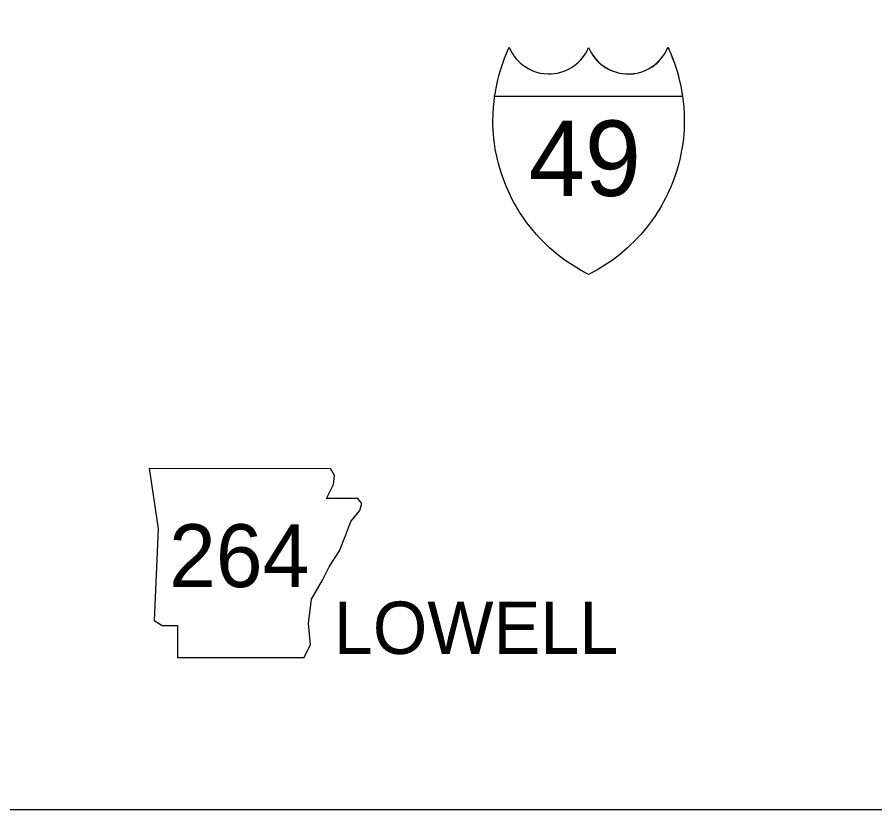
# Model space of a CAD drawing. Extents: x 6028647 to 6035072, y 5366486 to 5368495.
# Drawn here: x 6029148 to 6029256, y 5367916.3 to 5368016.2 of the extents above; entities that cross this region are included whole.
import ezdxf

# ---------------------------------------------------------------- set-up
doc = ezdxf.new("R2010")
doc.units = 0
for name, color, linetype in [('21', 7, 'Continuous'), ('22', 7, 'Continuous'), ('23', 7, 'Continuous'), ('25', 7, 'Continuous'), ('R_NoPlot', 7, 'Continuous')]:
    doc.layers.add(name, color=color, linetype=linetype)

msp = doc.modelspace()

# ---------------------------------------------------------------- linework, layer by layer
at = {"layer": '21'}
for p, q in [((6029164.66, 5367959.35), (6029165.81, 5367951.74)), ((6029188.01, 5367958.46), (6029187.48, 5367959.34)), ((6029187.88, 5367957.32), (6029188.01, 5367958.46)), ((6029187, 5367955.54), (6029187.88, 5367957.32)), ((6029190.93, 5367955.54), (6029187, 5367955.54)), ((6029191.44, 5367954.91), (6029190.93, 5367955.54)), ((6029191.18, 5367954.02), (6029191.44, 5367954.91)), ((6029190.04, 5367952.63), (6029191.18, 5367954.02)), ((6029189.41, 5367950.98), (6029190.04, 5367952.63)), ((6029165.81, 5367951.74), (6029165.3, 5367940.19)), ((6029188.65, 5367948.95), (6029189.41, 5367950.98)), ((6029187.38, 5367947.04), (6029188.65, 5367948.95)), ((6029186.49, 5367945.27), (6029187.38, 5367947.04)), ((6029185.09, 5367942.86), (6029186.49, 5367945.27)), ((6029184.71, 5367939.81), (6029185.09, 5367942.86)), ((6029165.3, 5367940.19), (6029166.31, 5367939.56)), ((6029166.31, 5367939.56), (6029168.22, 5367939.56)), ((6029168.22, 5367939.56), (6029168.22, 5367935.5)), ((6029184.97, 5367937.15), (6029184.71, 5367939.81)), ((6029184.2, 5367935.5), (6029184.97, 5367937.15)), ((6029168.22, 5367935.5), (6029184.2, 5367935.5))]:
    msp.add_line(p, q, dxfattribs=at)
msp.add_lwpolyline([(6029164.66, 5367959.35), (6029187.48, 5367959.34)], dxfattribs=at)
at = {"layer": '23'}
for points in [[(6029208.17, 5368006.18), (6029208.26, 5368006.75), (6029208.35, 5368007.25), (6029208.48, 5368007.89), (6029208.58, 5368008.31), (6029208.7, 5368008.81), (6029208.87, 5368009.4), (6029209.02, 5368009.89), (6029209.19, 5368010.39), (6029209.41, 5368011.01), (6029209.65, 5368011.59), (6029209.84, 5368012.05), (6029210, 5368012.4), (6029210.17, 5368012.02), (6029210.38, 5368011.65), (6029210.6, 5368011.32), (6029210.88, 5368010.94), (6029211.11, 5368010.69), (6029211.39, 5368010.42), (6029211.68, 5368010.18), (6029211.99, 5368009.96), (6029212.48, 5368009.66), (6029212.98, 5368009.43), (6029213.44, 5368009.27), (6029213.89, 5368009.15), (6029214.37, 5368009.07), (6029214.93, 5368009.03), (6029215.3, 5368009.04), (6029215.72, 5368009.08), (6029216.1, 5368009.15), (6029216.51, 5368009.24), (6029216.91, 5368009.38), (6029217.46, 5368009.62), (6029217.84, 5368009.83), (6029218.28, 5368010.13), (6029218.7, 5368010.49), (6029219, 5368010.8), (6029219.35, 5368011.22), (6029219.64, 5368011.65), (6029219.81, 5368011.96), (6029220, 5368012.36)], [(6029208.17, 5368006.18), (6029208.26, 5368006.75), (6029208.35, 5368007.25), (6029208.48, 5368007.89), (6029208.58, 5368008.31), (6029208.7, 5368008.81), (6029208.87, 5368009.4), (6029209.02, 5368009.89), (6029209.19, 5368010.39), (6029209.41, 5368011.01), (6029209.65, 5368011.59), (6029209.84, 5368012.05), (6029210, 5368012.4), (6029210.17, 5368012.02), (6029210.38, 5368011.65), (6029210.6, 5368011.32), (6029210.88, 5368010.94), (6029211.11, 5368010.69), (6029211.39, 5368010.42), (6029211.68, 5368010.18), (6029211.99, 5368009.96), (6029212.48, 5368009.66), (6029212.98, 5368009.43), (6029213.44, 5368009.27), (6029213.89, 5368009.15), (6029214.37, 5368009.07), (6029214.93, 5368009.03), (6029215.3, 5368009.04), (6029215.72, 5368009.08), (6029216.1, 5368009.15), (6029216.51, 5368009.24), (6029216.91, 5368009.38), (6029217.46, 5368009.62), (6029217.84, 5368009.83), (6029218.28, 5368010.13), (6029218.7, 5368010.49), (6029219, 5368010.8), (6029219.35, 5368011.22), (6029219.64, 5368011.65), (6029219.81, 5368011.96), (6029220, 5368012.36)], [(6029220, 5368012.36), (6029220.19, 5368011.96), (6029220.36, 5368011.65), (6029220.64, 5368011.22), (6029220.99, 5368010.8), (6029221.3, 5368010.49), (6029221.72, 5368010.13), (6029222.16, 5368009.83), (6029222.54, 5368009.62), (6029223.09, 5368009.38), (6029223.49, 5368009.24), (6029223.9, 5368009.15), (6029224.27, 5368009.08), (6029224.7, 5368009.04), (6029225.07, 5368009.03), (6029225.63, 5368009.07), (6029226.11, 5368009.15), (6029226.56, 5368009.27), (6029227.02, 5368009.43), (6029227.52, 5368009.66), (6029228.01, 5368009.96), (6029228.32, 5368010.18), (6029228.6, 5368010.42), (6029228.89, 5368010.69), (6029229.11, 5368010.94), (6029229.4, 5368011.32), (6029229.62, 5368011.65), (6029229.82, 5368012.02), (6029230, 5368012.4), (6029230.16, 5368012.05), (6029230.35, 5368011.59), (6029230.58, 5368011.01), (6029230.81, 5368010.39), (6029230.98, 5368009.89), (6029231.13, 5368009.4), (6029231.29, 5368008.81), (6029231.42, 5368008.31), (6029231.52, 5368007.89), (6029231.65, 5368007.25), (6029231.74, 5368006.75), (6029231.83, 5368006.18)], [(6029220, 5368012.35), (6029220.19, 5368011.95), (6029220.36, 5368011.65), (6029220.65, 5368011.21), (6029221, 5368010.79), (6029221.3, 5368010.48), (6029221.72, 5368010.12), (6029222.16, 5368009.82), (6029222.54, 5368009.61), (6029223.09, 5368009.37), (6029223.49, 5368009.24), (6029223.9, 5368009.14), (6029224.28, 5368009.07), (6029224.7, 5368009.03), (6029225.07, 5368009.03), (6029225.63, 5368009.06), (6029226.11, 5368009.14), (6029226.56, 5368009.26), (6029227.02, 5368009.42), (6029227.52, 5368009.66), (6029228.01, 5368009.95), (6029228.32, 5368010.17), (6029228.61, 5368010.41), (6029228.89, 5368010.69), (6029229.11, 5368010.94), (6029229.4, 5368011.31), (6029229.62, 5368011.64), (6029229.82, 5368012.01), (6029230, 5368012.4), (6029230.16, 5368012.04), (6029230.35, 5368011.59), (6029230.58, 5368011), (6029230.81, 5368010.38), (6029230.98, 5368009.88), (6029231.13, 5368009.39), (6029231.3, 5368008.8), (6029231.42, 5368008.3), (6029231.52, 5368007.88), (6029231.65, 5368007.24), (6029231.74, 5368006.74), (6029231.83, 5368006.17)], [(6029220, 5367983.77), (6029218.96, 5367984.33), (6029218.05, 5367984.88), (6029217.05, 5367985.55), (6029216.11, 5367986.26), (6029215.09, 5367987.13), (6029214.71, 5367987.49), (6029214.27, 5367987.92), (6029213.87, 5367988.33), (6029213.43, 5367988.81), (6029213, 5367989.32), (6029212.63, 5367989.76), (6029212.24, 5367990.27), (6029211.89, 5367990.76), (6029211.58, 5367991.22), (6029211.31, 5367991.63), (6029211.09, 5367991.99), (6029210.79, 5367992.5), (6029210.56, 5367992.91), (6029210.31, 5367993.4), (6029210.06, 5367993.9), (6029209.85, 5367994.36), (6029209.65, 5367994.8), (6029209.45, 5367995.31), (6029209.27, 5367995.77), (6029209.1, 5367996.25), (6029208.93, 5367996.76), (6029208.78, 5367997.28), (6029208.64, 5367997.77), (6029208.53, 5367998.24), (6029208.43, 5367998.66), (6029208.37, 5367998.97), (6029208.25, 5367999.58), (6029208.14, 5368000.27), (6029208.07, 5368000.85), (6029208.02, 5368001.46), (6029207.99, 5368001.96), (6029207.96, 5368002.58), (6029207.96, 5368003.17), (6029207.97, 5368003.82), (6029207.99, 5368004.25), (6029208.01, 5368004.64), (6029208.03, 5368004.89), (6029208.09, 5368005.53), (6029208.17, 5368006.18)], [(6029231.83, 5368006.18), (6029208.17, 5368006.18)], [(6029231.83, 5368006.18), (6029208.17, 5368006.18)], [(6029231.83, 5368006.18), (6029231.91, 5368005.53), (6029231.97, 5368004.89), (6029231.99, 5368004.64), (6029232.01, 5368004.25), (6029232.03, 5368003.82), (6029232.04, 5368003.17), (6029232.04, 5368002.58), (6029232.01, 5368001.96), (6029231.98, 5368001.46), (6029231.93, 5368000.85), (6029231.85, 5368000.27), (6029231.75, 5367999.58), (6029231.63, 5367998.97), (6029231.57, 5367998.66), (6029231.47, 5367998.24), (6029231.36, 5367997.77), (6029231.22, 5367997.28), (6029231.06, 5367996.76), (6029230.9, 5367996.25), (6029230.73, 5367995.77), (6029230.55, 5367995.31), (6029230.35, 5367994.8), (6029230.15, 5367994.36), (6029229.94, 5367993.9), (6029229.69, 5367993.4), (6029229.44, 5367992.91), (6029229.21, 5367992.5), (6029228.91, 5367991.99), (6029228.69, 5367991.63), (6029228.42, 5367991.22), (6029228.11, 5367990.76), (6029227.75, 5367990.27), (6029227.36, 5367989.76), (6029227, 5367989.32), (6029226.57, 5367988.81), (6029226.13, 5367988.33), (6029225.73, 5367987.92), (6029225.29, 5367987.49), (6029224.91, 5367987.13), (6029223.89, 5367986.26), (6029222.95, 5367985.55), (6029221.95, 5367984.88), (6029221.04, 5367984.33), (6029220, 5367983.77)]]:
    msp.add_lwpolyline(points, dxfattribs=at)
at = {"layer": 'R_NoPlot'}
msp.add_lwpolyline([(6028702.18, 5368445.48), (6029287.88, 5368445.48), (6029287.88, 5367916.32), (6028702.18, 5367916.32)], close=True, dxfattribs=at)

# ---------------------------------------------------------------- texts
at = {"layer": '21'}
msp.add_text('264', height=7.92, dxfattribs=at).set_placement((6029167.17, 5367944.38))
at = {"layer": '22'}
msp.add_text('49', height=9.504, dxfattribs=at).set_placement((6029212.46, 5367993.66))
at = {"layer": '25'}
msp.add_text('LOWELL', height=6.6, dxfattribs=at).set_placement((6029187.92, 5367935.96))

doc.saveas('drawing.dxf')
